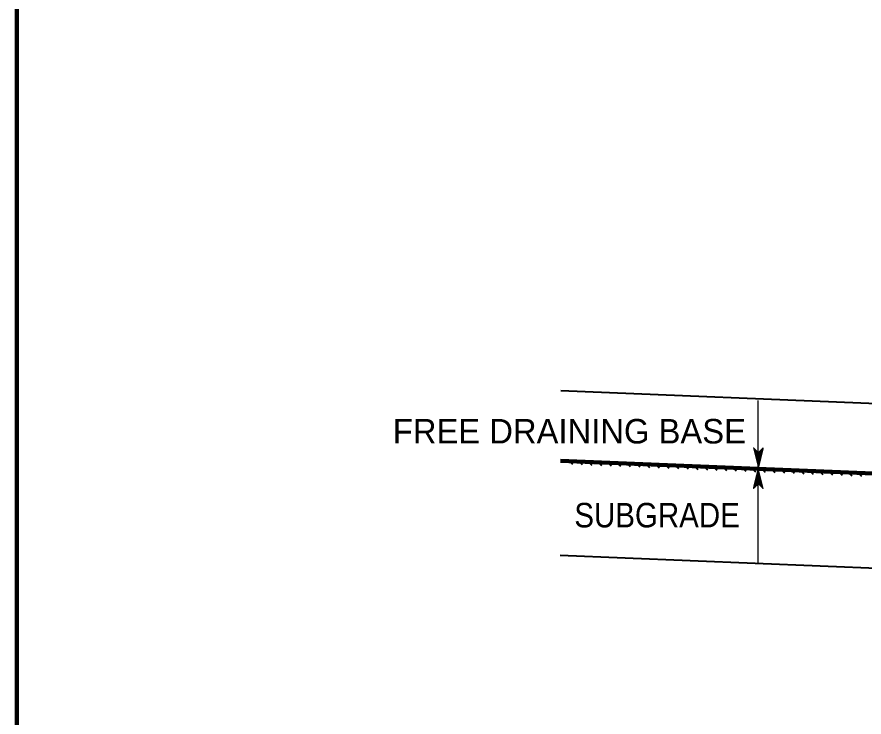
# Model space of a CAD drawing. Extents: x -48732 to -48696.6, y -117659.8 to -117637.8.
# Drawn here: x -48729.348 to -48725.971, y -117657.059 to -117654.269 of the extents above; entities that cross this region are included whole.
import ezdxf

# ---------------------------------------------------------------- set-up
doc = ezdxf.new("R2010")
doc.units = 0
doc.header["$LTSCALE"] = 0.048
for name, color, linetype, lineweight in [('1', 7, 'Continuous', 25), ('11', 7, 'Continuous', 25), ('24', 7, 'Continuous', 40)]:
    doc.layers.add(name, color=color, linetype=linetype, lineweight=lineweight)

msp = doc.modelspace()

# ---------------------------------------------------------------- linework, layer by layer
at = {"layer": '1', "lineweight": 158}
msp.add_line((-48729.34825, -117638.34817), (-48729.34825, -117659.34817), dxfattribs=at)
at = {"layer": '11'}
for p, q in [((-48726.39325, -117656.44575), (-48726.39325, -117655.79692)), ((-48726.41142, -117655.98692), (-48726.41158, -117655.98708)), ((-48726.41108, -117655.98725), (-48726.4115, -117655.98758)), ((-48726.41075, -117655.98758), (-48726.41142, -117655.98792)), ((-48726.41042, -117655.98792), (-48726.41125, -117655.98842)), ((-48726.41008, -117655.98825), (-48726.41108, -117655.98892)), ((-48726.40975, -117655.98858), (-48726.41108, -117655.98942)), ((-48726.40942, -117655.98883), (-48726.41092, -117655.98975)), ((-48726.40917, -117655.98917), (-48726.41075, -117655.99025)), ((-48726.40883, -117655.98942), (-48726.41075, -117655.99075)), ((-48726.40858, -117655.98975), (-48726.41058, -117655.99125)), ((-48726.40825, -117655.99008), (-48726.41042, -117655.99158)), ((-48726.40792, -117655.99042), (-48726.41033, -117655.99208)), ((-48726.40758, -117655.99075), (-48726.41025, -117655.99258)), ((-48726.40725, -117655.99108), (-48726.41008, -117655.993)), ((-48726.40692, -117655.99142), (-48726.40992, -117655.99342)), ((-48726.40658, -117655.99175), (-48726.40992, -117655.99392)), ((-48726.40625, -117655.992), (-48726.40975, -117655.99442)), ((-48726.40592, -117655.99233), (-48726.40958, -117655.99483)), ((-48726.40558, -117655.99258), (-48726.40958, -117655.99525)), ((-48726.40525, -117655.99292), (-48726.40942, -117655.99575)), ((-48726.405, -117655.99325), (-48726.40925, -117655.99625)), ((-48726.40467, -117655.99358), (-48726.40917, -117655.99667)), ((-48726.37425, -117655.99325), (-48726.38942, -117656.00358)), ((-48726.37408, -117655.99258), (-48726.38775, -117656.00192)), ((-48726.37392, -117655.99192), (-48726.38608, -117656.00025)), ((-48726.37375, -117655.99125), (-48726.38442, -117655.99858)), ((-48726.37358, -117655.99058), (-48726.38275, -117655.99692)), ((-48726.37342, -117655.98992), (-48726.38117, -117655.99525)), ((-48726.37325, -117655.98933), (-48726.37958, -117655.99358)), ((-48726.37317, -117655.98867), (-48726.37792, -117655.99192)), ((-48726.373, -117655.98808), (-48726.37625, -117655.99025)), ((-48726.37283, -117655.98742), (-48726.37458, -117655.98858)), ((-48726.37275, -117655.98675), (-48726.37292, -117655.98692)), ((-48726.40442, -117655.99392), (-48726.40908, -117655.99708)), ((-48726.40408, -117655.99425), (-48726.40892, -117655.99758)), ((-48726.40375, -117655.99458), (-48726.40875, -117655.99808)), ((-48726.40342, -117655.99492), (-48726.40875, -117655.9985)), ((-48726.40308, -117655.99525), (-48726.40858, -117655.99892)), ((-48726.40275, -117655.9955), (-48726.40842, -117655.99942)), ((-48726.40242, -117655.99575), (-48726.40842, -117655.99992)), ((-48726.40208, -117655.99608), (-48726.40825, -117656.00033)), ((-48726.40175, -117655.99642), (-48726.40808, -117656.00075)), ((-48726.40142, -117655.99675), (-48726.408, -117656.00125)), ((-48726.40108, -117655.99708), (-48726.40792, -117656.00175)), ((-48726.40075, -117655.99742), (-48726.40775, -117656.00217)), ((-48726.4005, -117655.99775), (-48726.40758, -117656.00258)), ((-48726.40017, -117655.99808), (-48726.40758, -117656.00308)), ((-48726.39992, -117655.99842), (-48726.40742, -117656.00358)), ((-48726.39958, -117655.99867), (-48726.40725, -117656.004)), ((-48726.39925, -117655.99892), (-48726.40725, -117656.00442)), ((-48726.39892, -117655.99925), (-48726.40708, -117656.00492)), ((-48726.39858, -117655.99958), (-48726.40692, -117656.00542)), ((-48726.39825, -117655.99992), (-48726.40683, -117656.00575)), ((-48726.39792, -117656.00025), (-48726.40675, -117656.00625)), ((-48726.39758, -117656.00058), (-48726.40658, -117656.00675)), ((-48726.39725, -117656.00092), (-48726.4065, -117656.00725)), ((-48726.39692, -117656.00125), (-48726.40642, -117656.00758)), ((-48726.39658, -117656.00158), (-48726.40625, -117656.00808)), ((-48726.39625, -117656.00183), (-48726.40608, -117656.00858)), ((-48726.396, -117656.00217), (-48726.40608, -117656.00908)), ((-48726.39575, -117656.00242), (-48726.40592, -117656.00942)), ((-48726.39542, -117656.00275), (-48726.40575, -117656.00992)), ((-48726.39508, -117656.00308), (-48726.40567, -117656.01042)), ((-48726.39475, -117656.00342), (-48726.40558, -117656.01092)), ((-48726.39442, -117656.00375), (-48726.40542, -117656.01125)), ((-48726.39408, -117656.00408), (-48726.40533, -117656.01175)), ((-48726.39375, -117656.00442), (-48726.40525, -117656.01225)), ((-48726.39342, -117656.00475), (-48726.40508, -117656.01267)), ((-48726.39308, -117656.00508), (-48726.40492, -117656.01308)), ((-48726.39275, -117656.00533), (-48726.40492, -117656.01358)), ((-48726.39242, -117656.00558), (-48726.40475, -117656.01408)), ((-48726.37458, -117655.99442), (-48726.40458, -117656.01492)), ((-48726.39208, -117656.00592), (-48726.40458, -117656.0145)), ((-48726.37475, -117655.99508), (-48726.40442, -117656.01542)), ((-48726.37492, -117655.99575), (-48726.40425, -117656.01592)), ((-48726.37508, -117655.99642), (-48726.40417, -117656.01633)), ((-48726.37525, -117655.99708), (-48726.40408, -117656.01675)), ((-48726.37542, -117655.99775), (-48726.40392, -117656.01725)), ((-48726.37558, -117655.99842), (-48726.40375, -117656.01775)), ((-48726.37575, -117655.999), (-48726.40375, -117656.01817)), ((-48726.37592, -117655.99958), (-48726.40358, -117656.01858)), ((-48726.37608, -117656.00025), (-48726.40342, -117656.01908)), ((-48726.37617, -117656.00092), (-48726.40342, -117656.01958)), ((-48726.37633, -117656.00158), (-48726.40325, -117656.02)), ((-48726.37642, -117656.00225), (-48726.40308, -117656.02042)), ((-48726.37658, -117656.00292), (-48726.403, -117656.02092)), ((-48726.37675, -117656.00358), (-48726.40292, -117656.02142)), ((-48726.37692, -117656.00417), (-48726.40275, -117656.02183)), ((-48726.37708, -117656.00475), (-48726.40258, -117656.02225)), ((-48726.37725, -117656.00542), (-48726.40258, -117656.02275)), ((-48726.37742, -117656.00608), (-48726.40242, -117656.02325)), ((-48726.37758, -117656.00675), (-48726.40225, -117656.02358)), ((-48726.37775, -117656.00742), (-48726.40225, -117656.02408)), ((-48726.37792, -117656.00808), (-48726.40208, -117656.02458)), ((-48726.37808, -117656.00875), (-48726.40192, -117656.02508)), ((-48726.37825, -117656.00933), (-48726.40183, -117656.02542)), ((-48726.37842, -117656.00992), (-48726.40175, -117656.02592)), ((-48726.37858, -117656.01058), (-48726.40158, -117656.02642)), ((-48726.37875, -117656.01125), (-48726.4015, -117656.02692)), ((-48726.37892, -117656.01192), (-48726.40142, -117656.02725)), ((-48726.37908, -117656.01258), (-48726.40125, -117656.02775)), ((-48726.37925, -117656.01325), (-48726.40108, -117656.02825)), ((-48726.37933, -117656.01392), (-48726.40108, -117656.02875)), ((-48726.3795, -117656.0145), (-48726.40092, -117656.02908)), ((-48726.37967, -117656.01508), (-48726.40075, -117656.02958)), ((-48726.37975, -117656.01575), (-48726.40075, -117656.03008)), ((-48726.37992, -117656.01642), (-48726.40058, -117656.0305)), ((-48726.38008, -117656.01708), (-48726.40042, -117656.03092)), ((-48726.38025, -117656.01775), (-48726.40033, -117656.03142)), ((-48726.38042, -117656.01842), (-48726.40025, -117656.03192)), ((-48726.38058, -117656.019), (-48726.40008, -117656.03233)), ((-48726.38075, -117656.01967), (-48726.39992, -117656.03275)), ((-48726.38092, -117656.02025), (-48726.39992, -117656.03325)), ((-48726.38108, -117656.02092), (-48726.39975, -117656.03375)), ((-48726.38125, -117656.02158), (-48726.39958, -117656.03417)), ((-48726.38142, -117656.02225), (-48726.39958, -117656.03458)), ((-48726.38158, -117656.02292), (-48726.39942, -117656.03508)), ((-48726.38175, -117656.02358), (-48726.39925, -117656.03558)), ((-48726.38192, -117656.02417), (-48726.39917, -117656.036)), ((-48726.38208, -117656.02475), (-48726.39908, -117656.03642)), ((-48726.38225, -117656.02542), (-48726.39892, -117656.03692)), ((-48726.38242, -117656.02608), (-48726.39875, -117656.03742)), ((-48726.38258, -117656.02675), (-48726.39875, -117656.03783)), ((-48726.38267, -117656.02742), (-48726.39858, -117656.03825)), ((-48726.37442, -117655.99383), (-48726.39108, -117656.00525)), ((-48726.38283, -117656.02808), (-48726.39842, -117656.03875)), ((-48726.383, -117656.02875), (-48726.39842, -117656.03925)), ((-48726.38308, -117656.02933), (-48726.39825, -117656.03967)), ((-48726.38325, -117656.02992), (-48726.39808, -117656.04008)), ((-48726.38342, -117656.03058), (-48726.398, -117656.04058)), ((-48726.38358, -117656.03125), (-48726.39792, -117656.04108)), ((-48726.38375, -117656.03192), (-48726.39775, -117656.04142)), ((-48726.38392, -117656.03258), (-48726.39758, -117656.04192)), ((-48726.38408, -117656.03325), (-48726.39758, -117656.04242)), ((-48726.38425, -117656.03392), (-48726.39742, -117656.04292)), ((-48726.38442, -117656.0345), (-48726.39725, -117656.04325)), ((-48726.38458, -117656.03508), (-48726.39725, -117656.04375)), ((-48726.38475, -117656.03575), (-48726.39708, -117656.04425)), ((-48726.38492, -117656.03642), (-48726.39692, -117656.04475)), ((-48726.38508, -117656.03708), (-48726.39683, -117656.04508)), ((-48726.38525, -117656.03775), (-48726.39675, -117656.04558)), ((-48726.38542, -117656.03842), (-48726.39658, -117656.04608)), ((-48726.38558, -117656.03908), (-48726.3965, -117656.04658)), ((-48726.38575, -117656.03967), (-48726.39642, -117656.04692)), ((-48726.38592, -117656.04025), (-48726.39625, -117656.04742)), ((-48726.386, -117656.04092), (-48726.39608, -117656.04792)), ((-48726.38617, -117656.04158), (-48726.39608, -117656.04842)), ((-48726.38625, -117656.04225), (-48726.39592, -117656.04875)), ((-48726.38642, -117656.04292), (-48726.39575, -117656.04925)), ((-48726.38658, -117656.04358), (-48726.39567, -117656.04975)), ((-48726.38675, -117656.04425), (-48726.39558, -117656.05017)), ((-48726.38692, -117656.04483), (-48726.39542, -117656.05058)), ((-48726.38708, -117656.04542), (-48726.39533, -117656.05108)), ((-48726.38725, -117656.04608), (-48726.39525, -117656.05158)), ((-48726.38742, -117656.04675), (-48726.39508, -117656.052)), ((-48726.38758, -117656.04742), (-48726.39492, -117656.05242)), ((-48726.38775, -117656.04808), (-48726.39492, -117656.05292)), ((-48726.38792, -117656.04875), (-48726.39475, -117656.05342)), ((-48726.38808, -117656.04933), (-48726.39458, -117656.05383)), ((-48726.38825, -117656.05), (-48726.39458, -117656.05425)), ((-48726.38842, -117656.05058), (-48726.39442, -117656.05475)), ((-48726.38858, -117656.05125), (-48726.39425, -117656.05525)), ((-48726.38875, -117656.05192), (-48726.39417, -117656.05567)), ((-48726.38892, -117656.05258), (-48726.39408, -117656.05608)), ((-48726.38908, -117656.05325), (-48726.39392, -117656.05658)), ((-48726.38917, -117656.05392), (-48726.39375, -117656.05708)), ((-48726.38933, -117656.0545), (-48726.39375, -117656.0575)), ((-48726.3895, -117656.05508), (-48726.39358, -117656.05792)), ((-48726.38958, -117656.05575), (-48726.39342, -117656.05842)), ((-48726.38975, -117656.05642), (-48726.39342, -117656.05892)), ((-48726.38992, -117656.05708), (-48726.39325, -117656.05933)), ((-48726.39008, -117656.05775), (-48726.39308, -117656.05975)), ((-48726.39025, -117656.05842), (-48726.393, -117656.06025)), ((-48726.39042, -117656.05908), (-48726.39292, -117656.06075)), ((-48726.39058, -117656.05967), (-48726.39275, -117656.06108)), ((-48726.39075, -117656.06025), (-48726.39258, -117656.06158)), ((-48726.39092, -117656.06092), (-48726.39258, -117656.06208)), ((-48726.40192, -117656.10525), (-48726.38692, -117656.09492)), ((-48726.40175, -117656.10467), (-48726.38692, -117656.09458)), ((-48726.40158, -117656.10408), (-48726.38708, -117656.09408)), ((-48726.40142, -117656.10342), (-48726.38725, -117656.09358)), ((-48726.40125, -117656.10275), (-48726.38725, -117656.09317)), ((-48726.40108, -117656.10208), (-48726.38742, -117656.09275)), ((-48726.40092, -117656.10142), (-48726.38758, -117656.09225)), ((-48726.40075, -117656.10075), (-48726.38767, -117656.09175)), ((-48726.40067, -117656.10008), (-48726.38775, -117656.09133)), ((-48726.4005, -117656.0995), (-48726.38792, -117656.09092)), ((-48726.40042, -117656.09892), (-48726.388, -117656.09042)), ((-48726.40025, -117656.09825), (-48726.38808, -117656.08992)), ((-48726.40008, -117656.09758), (-48726.38825, -117656.0895)), ((-48726.39992, -117656.09692), (-48726.38842, -117656.08908)), ((-48726.39975, -117656.09625), (-48726.38842, -117656.08858)), ((-48726.39958, -117656.09558), (-48726.38858, -117656.08808)), ((-48726.39942, -117656.09492), (-48726.38875, -117656.08767)), ((-48726.39925, -117656.09433), (-48726.38875, -117656.08725)), ((-48726.39908, -117656.09375), (-48726.38892, -117656.08675)), ((-48726.39892, -117656.09308), (-48726.38908, -117656.08625)), ((-48726.39875, -117656.09242), (-48726.38917, -117656.08583)), ((-48726.39858, -117656.09175), (-48726.38925, -117656.08542)), ((-48726.39842, -117656.09108), (-48726.38942, -117656.08492)), ((-48726.39825, -117656.09042), (-48726.38958, -117656.08442)), ((-48726.39808, -117656.08975), (-48726.38958, -117656.084)), ((-48726.39792, -117656.08917), (-48726.38975, -117656.08358)), ((-48726.39775, -117656.08858), (-48726.38992, -117656.08308)), ((-48726.39758, -117656.08792), (-48726.38992, -117656.08258)), ((-48726.3975, -117656.08725), (-48726.39008, -117656.08225)), ((-48726.39733, -117656.08658), (-48726.39025, -117656.08175)), ((-48726.39717, -117656.08592), (-48726.39033, -117656.08125)), ((-48726.39708, -117656.08525), (-48726.39042, -117656.08075)), ((-48726.39692, -117656.08458), (-48726.39058, -117656.08042)), ((-48726.39675, -117656.084), (-48726.39075, -117656.07992)), ((-48726.39658, -117656.08342), (-48726.39075, -117656.07942)), ((-48726.39642, -117656.08275), (-48726.39092, -117656.07892)), ((-48726.39625, -117656.08208), (-48726.39108, -117656.07858)), ((-48726.39608, -117656.08142), (-48726.39108, -117656.07808)), ((-48726.39592, -117656.08075), (-48726.39125, -117656.07758)), ((-48726.39575, -117656.08008), (-48726.39142, -117656.07708)), ((-48726.39558, -117656.0795), (-48726.3915, -117656.07675)), ((-48726.39542, -117656.07883), (-48726.39158, -117656.07625)), ((-48726.39525, -117656.07825), (-48726.39175, -117656.07575)), ((-48726.39508, -117656.07758), (-48726.39192, -117656.07525)), ((-48726.39492, -117656.07692), (-48726.39192, -117656.07492)), ((-48726.39475, -117656.07625), (-48726.39208, -117656.07442)), ((-48726.39458, -117656.07558), (-48726.39225, -117656.07392)), ((-48726.39442, -117656.07492), (-48726.39225, -117656.0735)), ((-48726.39425, -117656.07433), (-48726.39242, -117656.07308)), ((-48726.39417, -117656.07375), (-48726.39258, -117656.07258)), ((-48726.394, -117656.07308), (-48726.39267, -117656.07208)), ((-48726.39383, -117656.07242), (-48726.39275, -117656.07167)), ((-48726.39375, -117656.07175), (-48726.39292, -117656.07125)), ((-48726.39358, -117656.07108), (-48726.393, -117656.07075)), ((-48726.39342, -117656.07042), (-48726.39308, -117656.07025)), ((-48726.39108, -117656.06158), (-48726.39242, -117656.06258)), ((-48726.39125, -117656.06225), (-48726.39225, -117656.06292)), ((-48726.39142, -117656.06292), (-48726.39225, -117656.06342)), ((-48726.39158, -117656.06358), (-48726.39208, -117656.06392)), ((-48726.39175, -117656.06425), (-48726.39192, -117656.06442)), ((-48726.4105, -117656.14017), (-48726.38058, -117656.11967)), ((-48726.41033, -117656.1395), (-48726.38075, -117656.11925)), ((-48726.41017, -117656.13892), (-48726.38075, -117656.11875)), ((-48726.41008, -117656.13825), (-48726.38092, -117656.11825)), ((-48726.40992, -117656.13758), (-48726.38108, -117656.11792)), ((-48726.40975, -117656.13692), (-48726.38108, -117656.11742)), ((-48726.40958, -117656.13625), (-48726.38125, -117656.11692)), ((-48726.40942, -117656.13558), (-48726.38142, -117656.11642)), ((-48726.40925, -117656.135), (-48726.3815, -117656.11608)), ((-48726.40908, -117656.13442), (-48726.38158, -117656.11558)), ((-48726.40892, -117656.13375), (-48726.38175, -117656.11508)), ((-48726.40875, -117656.13308), (-48726.38192, -117656.11458)), ((-48726.40858, -117656.13242), (-48726.38192, -117656.11425)), ((-48726.40842, -117656.13175), (-48726.38208, -117656.11375)), ((-48726.40825, -117656.13108), (-48726.38225, -117656.11325)), ((-48726.40808, -117656.13042), (-48726.38225, -117656.11275)), ((-48726.40792, -117656.12983), (-48726.38242, -117656.11242)), ((-48726.40775, -117656.12925), (-48726.38258, -117656.11192)), ((-48726.40758, -117656.12858), (-48726.38267, -117656.11142)), ((-48726.40742, -117656.12792), (-48726.38275, -117656.111)), ((-48726.40733, -117656.12725), (-48726.38292, -117656.11058)), ((-48726.40717, -117656.12658), (-48726.383, -117656.11008)), ((-48726.407, -117656.12592), (-48726.38308, -117656.10958)), ((-48726.40692, -117656.12525), (-48726.38325, -117656.10917)), ((-48726.40675, -117656.12467), (-48726.38342, -117656.10875)), ((-48726.40658, -117656.12408), (-48726.38342, -117656.10825)), ((-48726.40642, -117656.12342), (-48726.38358, -117656.10775)), ((-48726.40625, -117656.12275), (-48726.38375, -117656.10733)), ((-48726.40608, -117656.12208), (-48726.38375, -117656.10692)), ((-48726.40592, -117656.12142), (-48726.38392, -117656.10642)), ((-48726.40575, -117656.12075), (-48726.38408, -117656.10592)), ((-48726.40558, -117656.12008), (-48726.38417, -117656.1055)), ((-48726.40542, -117656.1195), (-48726.38425, -117656.10508)), ((-48726.40525, -117656.11892), (-48726.38442, -117656.10458)), ((-48726.40508, -117656.11825), (-48726.38458, -117656.10408)), ((-48726.40492, -117656.11758), (-48726.38458, -117656.10367)), ((-48726.40475, -117656.11692), (-48726.38475, -117656.10325)), ((-48726.40458, -117656.11625), (-48726.38492, -117656.10275)), ((-48726.40442, -117656.11558), (-48726.38492, -117656.10225)), ((-48726.40425, -117656.11492), (-48726.38508, -117656.10183)), ((-48726.40408, -117656.11433), (-48726.38525, -117656.10142)), ((-48726.404, -117656.11375), (-48726.38533, -117656.10092)), ((-48726.40383, -117656.11308), (-48726.38542, -117656.10042)), ((-48726.40367, -117656.11242), (-48726.38558, -117656.10008)), ((-48726.40358, -117656.11175), (-48726.38575, -117656.09958)), ((-48726.40342, -117656.11108), (-48726.38575, -117656.09908)), ((-48726.40325, -117656.11042), (-48726.38592, -117656.09858)), ((-48726.40308, -117656.10983), (-48726.38608, -117656.09825)), ((-48726.40292, -117656.10917), (-48726.38608, -117656.09775)), ((-48726.40275, -117656.10858), (-48726.38625, -117656.09725)), ((-48726.40258, -117656.10792), (-48726.38642, -117656.09675)), ((-48726.40242, -117656.10725), (-48726.3865, -117656.09642)), ((-48726.40225, -117656.10658), (-48726.38658, -117656.09592)), ((-48726.40208, -117656.10592), (-48726.38675, -117656.09542)), ((-48726.39292, -117656.12867), (-48726.38042, -117656.12008)), ((-48726.39258, -117656.129), (-48726.38033, -117656.12058)), ((-48726.39225, -117656.12925), (-48726.38025, -117656.12108)), ((-48726.39192, -117656.12958), (-48726.38008, -117656.1215)), ((-48726.39158, -117656.12992), (-48726.37992, -117656.12192)), ((-48726.39133, -117656.13025), (-48726.37992, -117656.12242)), ((-48726.391, -117656.13058), (-48726.37975, -117656.12292)), ((-48726.39075, -117656.13092), (-48726.37958, -117656.12333)), ((-48726.39042, -117656.13125), (-48726.37958, -117656.12375)), ((-48726.39008, -117656.13158), (-48726.37942, -117656.12425)), ((-48726.38975, -117656.13192), (-48726.37925, -117656.12475)), ((-48726.38942, -117656.13217), (-48726.37917, -117656.12517)), ((-48726.38908, -117656.13242), (-48726.37908, -117656.12558)), ((-48726.38875, -117656.13275), (-48726.37892, -117656.12608)), ((-48726.38842, -117656.13308), (-48726.37875, -117656.12658)), ((-48726.38808, -117656.13342), (-48726.37875, -117656.127)), ((-48726.38775, -117656.13375), (-48726.37858, -117656.12742)), ((-48726.38742, -117656.13408), (-48726.37842, -117656.12792)), ((-48726.38708, -117656.13442), (-48726.37842, -117656.12842)), ((-48726.38683, -117656.13475), (-48726.37825, -117656.12883)), ((-48726.41242, -117656.14792), (-48726.41208, -117656.14775)), ((-48726.41225, -117656.14725), (-48726.4105, -117656.14608)), ((-48726.41208, -117656.14658), (-48726.40892, -117656.14442)), ((-48726.41192, -117656.14592), (-48726.40725, -117656.14275)), ((-48726.41175, -117656.14525), (-48726.40558, -117656.14108)), ((-48726.41158, -117656.14467), (-48726.40392, -117656.13942)), ((-48726.41142, -117656.14408), (-48726.40225, -117656.13775)), ((-48726.41125, -117656.14342), (-48726.40058, -117656.13608)), ((-48726.41108, -117656.14275), (-48726.39892, -117656.13442)), ((-48726.41092, -117656.14208), (-48726.39733, -117656.13275)), ((-48726.41075, -117656.14142), (-48726.39575, -117656.13108)), ((-48726.41058, -117656.14075), (-48726.39408, -117656.12942)), ((-48726.38658, -117656.13508), (-48726.37808, -117656.12925)), ((-48726.38625, -117656.13533), (-48726.378, -117656.12975)), ((-48726.38592, -117656.13567), (-48726.37792, -117656.13025)), ((-48726.38558, -117656.13592), (-48726.37775, -117656.13058)), ((-48726.38525, -117656.13625), (-48726.37767, -117656.13108)), ((-48726.38492, -117656.13658), (-48726.37758, -117656.13158)), ((-48726.38458, -117656.13692), (-48726.37742, -117656.13208)), ((-48726.38425, -117656.13725), (-48726.37725, -117656.13242)), ((-48726.38392, -117656.13758), (-48726.37725, -117656.13292)), ((-48726.38358, -117656.13792), (-48726.37708, -117656.13342)), ((-48726.38325, -117656.13825), (-48726.37692, -117656.13392)), ((-48726.38292, -117656.1385), (-48726.37692, -117656.13425)), ((-48726.38267, -117656.13883), (-48726.37675, -117656.13475)), ((-48726.38233, -117656.13908), (-48726.37658, -117656.13525)), ((-48726.38208, -117656.13942), (-48726.3765, -117656.13575)), ((-48726.38175, -117656.13975), (-48726.37642, -117656.13608)), ((-48726.38142, -117656.14008), (-48726.37625, -117656.13658)), ((-48726.38108, -117656.14042), (-48726.37608, -117656.13708)), ((-48726.38075, -117656.14075), (-48726.37608, -117656.13758)), ((-48726.38042, -117656.14108), (-48726.37592, -117656.13792)), ((-48726.38008, -117656.14142), (-48726.37575, -117656.13842)), ((-48726.37975, -117656.14175), (-48726.37575, -117656.13892)), ((-48726.37942, -117656.142), (-48726.37558, -117656.13933)), ((-48726.37908, -117656.14225), (-48726.37542, -117656.13975)), ((-48726.37875, -117656.14258), (-48726.37533, -117656.14025)), ((-48726.37842, -117656.14292), (-48726.37525, -117656.14075)), ((-48726.37817, -117656.14325), (-48726.37508, -117656.14117)), ((-48726.37783, -117656.14358), (-48726.37492, -117656.14158)), ((-48726.37758, -117656.14392), (-48726.37492, -117656.14208)), ((-48726.37725, -117656.14425), (-48726.37475, -117656.14258)), ((-48726.37692, -117656.14458), (-48726.37458, -117656.143)), ((-48726.37658, -117656.14492), (-48726.37458, -117656.14342)), ((-48726.37625, -117656.14517), (-48726.37442, -117656.14392)), ((-48726.37592, -117656.14542), (-48726.37425, -117656.14442)), ((-48726.37558, -117656.14575), (-48726.37417, -117656.14483)), ((-48726.37525, -117656.14608), (-48726.37408, -117656.14525)), ((-48726.37492, -117656.14642), (-48726.37392, -117656.14575)), ((-48726.37458, -117656.14675), (-48726.37383, -117656.14625)), ((-48726.37425, -117656.14708), (-48726.37375, -117656.14667)), ((-48726.374, -117656.14742), (-48726.37358, -117656.14708)), ((-48726.37367, -117656.14775), (-48726.37342, -117656.14758))]:
    msp.add_line(p, q, dxfattribs=at)
for points in [[(-48726.39192, -117656.06475), (-48726.37267, -117655.98658), (-48726.39192, -117656.00608), (-48726.41175, -117655.98658)], [(-48726.39325, -117656.06992), (-48726.41242, -117656.148), (-48726.39308, -117656.1285), (-48726.37342, -117656.148)]]:
    msp.add_lwpolyline(points, close=True, dxfattribs=at)
at = {"layer": '24'}
for p, q in [((-48727.18042, -117655.75775), (-48723.94175, -117655.89058)), ((-48727.13208, -117656.05258), (-48727.14575, -117656.039)), ((-48727.09375, -117656.05417), (-48727.10725, -117656.04058)), ((-48727.05525, -117656.05575), (-48727.06892, -117656.04217)), ((-48727.01692, -117656.05725), (-48727.03042, -117656.04375)), ((-48726.97842, -117656.05892), (-48726.99208, -117656.04525)), ((-48726.94008, -117656.06042), (-48726.95367, -117656.04692)), ((-48726.90167, -117656.06208), (-48726.91525, -117656.04842)), ((-48726.86325, -117656.06358), (-48726.87692, -117656.05008)), ((-48726.82492, -117656.06525), (-48726.83842, -117656.05158)), ((-48726.78642, -117656.06675), (-48726.80008, -117656.05325)), ((-48726.74808, -117656.06842), (-48726.76158, -117656.05475)), ((-48726.70958, -117656.06992), (-48726.72325, -117656.05633)), ((-48726.67125, -117656.0715), (-48726.68483, -117656.05792)), ((-48726.63283, -117656.07308), (-48726.64642, -117656.0595)), ((-48726.59442, -117656.07458), (-48726.60808, -117656.06108)), ((-48726.55608, -117656.07625), (-48726.56958, -117656.06258)), ((-48726.51758, -117656.07775), (-48726.53125, -117656.06425)), ((-48726.47925, -117656.07942), (-48726.49275, -117656.06575)), ((-48726.44075, -117656.08092), (-48726.45442, -117656.06742)), ((-48726.40242, -117656.08258), (-48726.416, -117656.06892)), ((-48726.364, -117656.08408), (-48726.37758, -117656.07058)), ((-48726.32558, -117656.08575), (-48726.33925, -117656.07208)), ((-48726.28725, -117656.08725), (-48726.30075, -117656.07367)), ((-48726.24875, -117656.08883), (-48726.26242, -117656.07525)), ((-48726.21042, -117656.09042), (-48726.22392, -117656.07683)), ((-48726.17192, -117656.09192), (-48726.18558, -117656.07842)), ((-48726.13358, -117656.09358), (-48726.14717, -117656.07992)), ((-48726.09517, -117656.09508), (-48726.10875, -117656.08158)), ((-48726.05675, -117656.09675), (-48726.07042, -117656.08308)), ((-48726.01842, -117656.09825), (-48726.03192, -117656.08475)), ((-48725.97992, -117656.09992), (-48725.99358, -117656.08625)), ((-48727.18275, -117656.41392), (-48725.551, -117656.48092))]:
    msp.add_line(p, q, dxfattribs=at)
at = {"layer": '24', "lineweight": 106}
msp.add_line((-48727.18058, -117656.03758), (-48725.53792, -117656.10492), dxfattribs=at)

# ---------------------------------------------------------------- texts
at = {"layer": '11'}
msp.add_text('FREE DRAINING BASE', height=0.09767, dxfattribs=at).set_placement((-48727.84975, -117655.96867))
at = {"layer": '11', "width": 0.9}
msp.add_text('SUBGRADE', height=0.09767, dxfattribs=at).set_placement((-48727.12608, -117656.303))

doc.saveas('drawing.dxf')
